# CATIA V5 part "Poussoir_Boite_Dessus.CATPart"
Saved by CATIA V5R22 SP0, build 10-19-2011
Part number: Poussoir_Boite_Dessus
Bounding box of the stored display mesh (mm): x -80 to 80, y -88 to 88, z 0 to 5
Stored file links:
  D:\CAO_PER_MODIF_2025\CAO_PER_pick&place_2024P\Sous_Ensemble_Boite\Verin\Poussoir\Poussoir_Boite_Dessus.CATPart
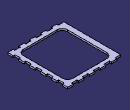
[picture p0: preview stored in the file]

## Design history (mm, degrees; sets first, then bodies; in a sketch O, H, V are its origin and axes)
Body1 (main body)
  Sketch1 on xy-plane, origin (0, 0, 0), H (1, 0, 0), V (0, 1, 0)
    line L1 (-80, 88) -> (80, 88)
    line L2 (80, 88) -> (80, -88)
    line L3 (80, -88) -> (-80, -88)
    line L4 (-80, -88) -> (-80, 88)
    line L5 (-50, 73) -> (50, 73)
    line L6 (65, 58) -> (65, -58)
    line L7 (50, -73) -> (-50, -73)
    line L8 (-65, -58) -> (-65, 58)
    arc A1 centre (-50, 58) radius 15 from (-65, 58) to (-50, 73) cw
    arc A2 centre (50, 58) radius 15 from (50, 73) to (65, 58) cw
    arc A3 centre (50, -58) radius 15 from (65, -58) to (50, -73) cw
    arc A4 centre (-50, -58) radius 15 from (-65, -58) to (-50, -73) ccw
    length L1 = 160
    length L2 = 176
    distance L6 L2 = 15
    distance L7 L3 = 15
    radius A1 = 15
    radius A2 = 15
    radius A3 = 15
    radius A4 = 15
    horizontal: L1 H, L3 H, L5 H, L7 H
    vertical: L2 V, L4 V, L6 V, L8 V
    equidistance: L3 L1 O, L2 L4 O, L6 L8 O, L7 L5 O
    tangency: A1 L8, A1 L5, A2 L5, A2 L6, A3 L6, A3 L7, A4 L8, A4 L7
  Pad1: profile Sketch1, direction (0, 0, 1), length 5
  Sketch2 on end face of Pad1, origin (0, 0, 5), H (1, 0, 0), V (0, 1, 0)
    point P1 (-80, -83)
    line L1 (-80, -83) -> (-64, -83)
    line L2 (-64, -83) -> (-64, -88)
    line L3 (-64, -88) -> (-80, -88)
    line L4 (-80, -88) -> (-80, -83)
    point P2 (-64, -83)
    point P3 (-64, -88)
    point P4 (-80, -88)
    reference projected line E1 (-80, 88) -> (-80, -88) from edge [face of Pad1 from Sketch1.L4 | end face of Pad1]
    reference projected line E2 (-80, -88) -> (80, -88) from edge [face of Pad1 from Sketch1.L3 | end face of Pad1]
    point P5 (-80, 83)
    point P6 (-64, 83)
    point P7 (-64, 88)
    point P8 (-80, 88)
    line L5 (-80, 83) -> (-64, 83)
    line L6 (-64, 83) -> (-64, 88)
    line L7 (-64, 88) -> (-80, 88)
    line L8 (-80, 88) -> (-80, 83)
    length L2 = 5
    length L1 = 16
    horizontal: L1 H, L3 H
    vertical: L2 V, L4 V
    coincidence: L4 E1, L3 E2
    symmetry: P1 P5 H, P2 P6 H, P3 P7 H, P4 P8 H, L1 L5 H, L2 L6 H, L3 L7 H, L4 L8 H
  Pocket1: profile Sketch2, direction (0, 0, -1), through (limit type 6)
  RectPattern1: of Pocket1, direction 1 instances 5, spacing 32, along end face of Pad1
  Sketch3 on end face of Pad1, origin (0, 0, 5), H (1, 0, 0), V (0, 1, 0)
    line L1 (80, -72) -> (75, -72)
    line L2 (75, -72) -> (75, -56)
    line L3 (75, -56) -> (80, -56)
    line L4 (80, -56) -> (80, -72)
    reference projected line E1 (80, -88) -> (80, 88) from edge [face of Pad1 from Sketch1.L2 | end face of Pad1]
    reference projected line E2 (-80, -88) -> (80, -88) from edge [face of Pad1 from Sketch1.L3 | end face of Pad1]
    length L3 = 5
    length L2 = 16
    distance L1 E2 = 16
    horizontal: L1 H, L3 H
    vertical: L2 V, L4 V
    coincidence: L4 E1
  Pocket2: profile Sketch3, direction (0, 0, -1), through (limit type 6)
  RectPattern2: of Pocket2, direction 1 instances 1, spacing 32, along end face of Pad1, direction 2 instances 5, spacing 32, along end face of Pad1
